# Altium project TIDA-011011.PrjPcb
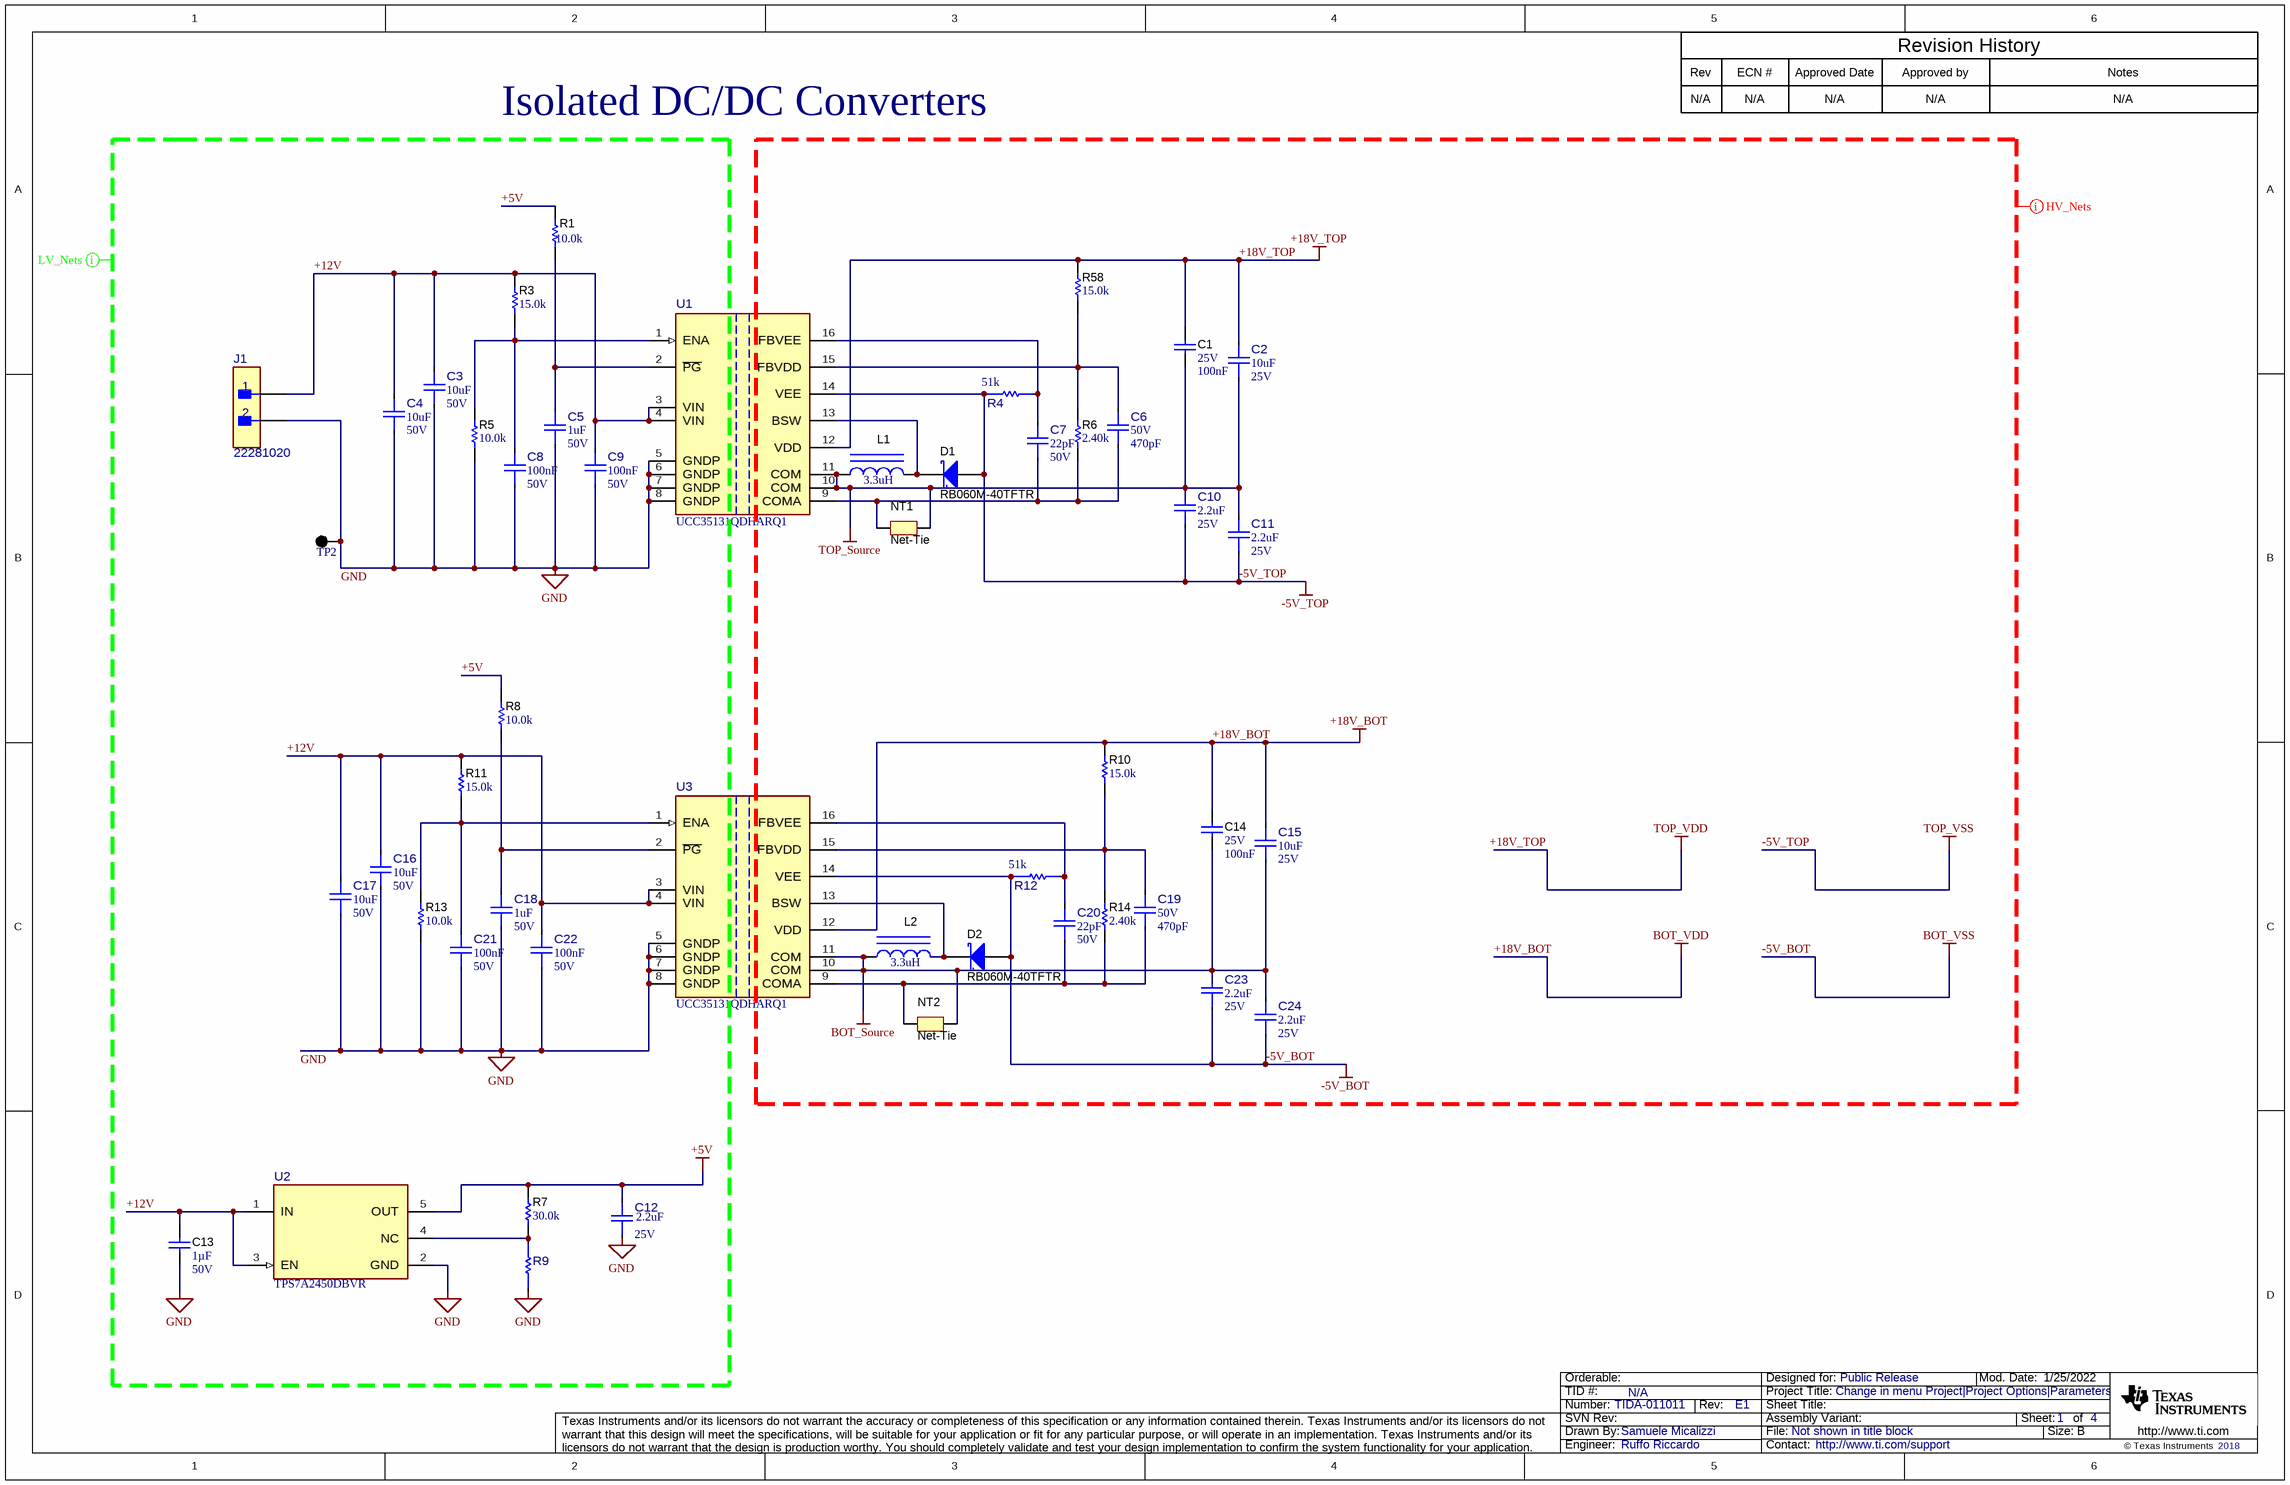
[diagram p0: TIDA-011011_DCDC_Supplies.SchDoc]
DrawnBy: Samuele Micalizzi; TID: N/A; TechSupport: http://www.ti.com/support; SCH_Rev: E1; PRJ_Title: Change in menu Project|Project Options|Parameters; PRJ_Number: TIDA-011011; PRJ_Engineer: Ruffo Riccardo; PRJ_Customer: Public Release; PCB_Rev: E1; PCB_Layout: Samuele Micalizzi; CopyrightYear: 2018
4 sheets, 172 parts. Net scope: global (net labels, ports and power ports of the same name join across sheets).
Board file: TIDA-011011.PcbDoc
Sheets:
  TIDA-011011_DCDC_Supplies.SchDoc
  TIDA-011011_Gate_Drivers.SchDoc
  TIDA-011011_BlankSheet.SchDoc
  TIDA-011011_Hardware.SchDoc

## Sheet TIDA-011011_DCDC_Supplies.SchDoc
size 431 x 279 mm; Date: Not shown in title block; ApprovedBy: Not shown in title block; CheckedBy: Not shown in title block; Author: Not shown in title block; CompanyName: Not shown in title block; Engineer: Not shown in title block; Organization: Not shown in title block; Address1: Not shown in title block; Address2: Not shown in title block; Address3: Not shown in title block; Address4: Not shown in title block; DocumentNumber: 1; Revision: Use project parameter SCH_Rev; SheetNumber: 1; SheetTotal: 4; PageSetup: Record=PageOptions¦CenterHorizontal=True¦CenterVertical=True¦PrintScale=1.00¦XCorrection=1.00¦YCorrection=1.00¦PrintKind=0¦BorderSize=5000000¦LeftOffset=0¦BottomOffset=0¦Orientation=2¦PaperLength=1000¦PaperWidth=1000¦Scale=100¦PaperSource=15¦PrintQuality=600¦MediaType=1¦DitherType=10¦PaperKind=Letter¦PrintScaleMode=1

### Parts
C1  VDC_V: 25V  Cap_F: 100nF  [0603]  (hidden comment: GCM188R71E104KA57D)
C2  ValueDisplayed: 10uF  VDC_V: 25V  [FP-KGM31HR71E106KU_1206-MFG]  (hidden comment: KGM31HR71E106KU)
C3  ValueDisplayed: 10uF  VDC_V: 50V  [FP-GMC31X7R106K50NT_1206-MFG]  (hidden comment: GMC31X7R106K50NT)
C4  ValueDisplayed: 10uF  VDC_V: 50V  [FP-GMC31X7R106K50NT_1206-MFG]  (hidden comment: GMC31X7R106K50NT)
C5  ValueDisplayed: 1uF  VDC_V: 50V  [FP-C1206C105J5RECAUTO_1206-MFG]  (hidden comment: C1206C105J5RECAUTO)
C6  VDC_V: 50V  ValueDisplayed: 470pF  [FP-C0603X471F5GACTU_0603-MFG]  (hidden comment: C0603X471F5GACTU)
C7  ValueDisplayed: 22pF  VDC_V: 50V  [FP-VJ0603D220JLAAJ32_0603-IPC_C]  (hidden comment: VJ0603D220JLAAJ32)
C8  Cap_F: 100nF  VDC_V: 50V  [FP-KGM15BR71H104JT_0603-MFG]  (hidden comment: KGM15BR71H104JT)
C9  Cap_F: 100nF  VDC_V: 50V  [FP-KGM15BR71H104JT_0603-MFG]  (hidden comment: KGM15BR71H104JT)
C10  ValueDisplayed: 2.2uF  VDC_V: 25V  [FP-GRT188C71E225KE13D_0603-MFG]  (hidden comment: GRT188C71E225KE13D)
C11  ValueDisplayed: 2.2uF  VDC_V: 25V  [FP-CGA5L2X7R1E225K160AA_1206-MFG]  (hidden comment: CGA5L2X7R1E225K160AA)
C12  ValueDisplayed: 2.2uF  VDC_V: 25V  [FP-GRT188C71E225KE13D_0603-MFG]  (hidden comment: GRT188C71E225KE13D)
C13  Cap_F: 1µF  VDC_V: 50V  [0603]  (hidden comment: UMK107AB7105KA-T)
C14  VDC_V: 25V  Cap_F: 100nF  [0603]  (hidden comment: GCM188R71E104KA57D)
C15  ValueDisplayed: 10uF  VDC_V: 25V  [FP-KGM31HR71E106KU_1206-MFG]  (hidden comment: KGM31HR71E106KU)
C16  ValueDisplayed: 10uF  VDC_V: 50V  [FP-GMC31X7R106K50NT_1206-MFG]  (hidden comment: GMC31X7R106K50NT)
C17  ValueDisplayed: 10uF  VDC_V: 50V  [FP-GMC31X7R106K50NT_1206-MFG]  (hidden comment: GMC31X7R106K50NT)
C18  ValueDisplayed: 1uF  VDC_V: 50V  [FP-C1206C105J5RECAUTO_1206-MFG]  (hidden comment: C1206C105J5RECAUTO)
C19  VDC_V: 50V  ValueDisplayed: 470pF  [FP-C0603X471F5GACTU_0603-MFG]  (hidden comment: C0603X471F5GACTU)
C20  ValueDisplayed: 22pF  VDC_V: 50V  [FP-VJ0603D220JLAAJ32_0603-IPC_C]  (hidden comment: VJ0603D220JLAAJ32)
C21  Cap_F: 100nF  VDC_V: 50V  [FP-KGM15BR71H104JT_0603-MFG]  (hidden comment: KGM15BR71H104JT)
C22  Cap_F: 100nF  VDC_V: 50V  [FP-KGM15BR71H104JT_0603-MFG]  (hidden comment: KGM15BR71H104JT)
C23  ValueDisplayed: 2.2uF  VDC_V: 25V  [FP-GRT188C71E225KE13D_0603-MFG]  (hidden comment: GRT188C71E225KE13D)
C24  ValueDisplayed: 2.2uF  VDC_V: 25V  [FP-CGA5L2X7R1E225K160AA_1206-MFG]  (hidden comment: CGA5L2X7R1E225K160AA)
D1  RB060M-40TFTR  [SOD-123]
D2  RB060M-40TFTR  [SOD-123]
J1  22281020  [FP-22281020_HDR2-MFG]
L1  ValueDisplayed: 3.3uH  [0603]  (hidden comment: AIML-0603-3R3K-T)
L2  ValueDisplayed: 3.3uH  [0603]  (hidden comment: AIML-0603-3R3K-T)
NT1  Net-Tie  [Net-Tie_0805_HV_NoOverlay]  (net tie, no BOM)
NT2  Net-Tie  [Net-Tie_0805_HV_NoOverlay]  (net tie, no BOM)
R1  ValueDisplayed: 10.0k  [0603]  (hidden comment: RT0603DRE0710KL)
R3  ValueDisplayed: 15.0k  [0603]  (hidden comment: RT0603BRD0715KL)
R4  value 51k  [FP-ERA-3AED513V_0603-MFG]  (hidden comment: ERA-3AED513V)
R5  ValueDisplayed: 10.0k  [0603]  (hidden comment: RT0603DRE0710KL)
R6  ValueDisplayed: 2.40k  [0603]  (hidden comment: RT0603DRE072K4L)
R7  ValueDisplayed: 30.0k  [0603]  (hidden comment: RG1608P-303-B-T5)
R8  ValueDisplayed: 10.0k  [0603]  (hidden comment: RT0603DRE0710KL)
R9  P2TC0603D1002LNTA  [FP-P2TC0603D1002LNTA_0603-MFG]  (value not drawn)
R10  ValueDisplayed: 15.0k  [0603]  (hidden comment: RT0603BRD0715KL)
R11  ValueDisplayed: 15.0k  [0603]  (hidden comment: RT0603BRD0715KL)
R12  value 51k  [FP-ERA-3AED513V_0603-MFG]  (hidden comment: ERA-3AED513V)
R13  ValueDisplayed: 10.0k  [0603]  (hidden comment: RT0603DRE0710KL)
R14  ValueDisplayed: 2.40k  [0603]  (hidden comment: RT0603DRE072K4L)
R58  ValueDisplayed: 15.0k  [0603]  (hidden comment: RT0603BRD0715KL)
TP2  5011  [Keystone5011]  (value not drawn)
U1  UCC35131QDHARQ1  [DHA0016A-MFG]
U2  TPS7A2450DBVR  [DBV0005A-MFG]
U3  UCC35131QDHARQ1  [DHA0016A-MFG]

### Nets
+5V: C12.2 R1.2 R7.2 R8.2 U2.5(OUT)
+12V: C3.2 C4.2 C9.2 C13.1 C16.2 C17.2 C22.2 J1.1 R3.2 R11.2 U1.3(VIN) U1.4(VIN) U2.1(IN) U2.3(EN) U3.3(VIN) U3.4(VIN)
+18V_BOT: C14.1 C15.2 R10.2 U3.12(VDD)  [also labelled BOT_VDD]
+18V_TOP: C1.1 C2.2 R58.2 U1.12(VDD)  [also labelled TOP_VDD]
-5V_BOT: C23.1 C24.1 D2.2(A) R12.1 U3.14(VEE)  [also labelled BOT_VSS]
-5V_TOP: C10.1 C11.1 D1.2(A) R4.1 U1.14(VEE)  [also labelled TOP_VSS]
BOT_Source: C14.2 C15.1 C23.2 C24.2 L2.1 NT2.2 U3.10(COM) U3.11(COM)
GND: C3.1 C4.1 C5.1 C8.1 C9.1 C12.1 C13.2 C16.1 C17.1 C18.1 C21.1 C22.1 J1.2 R5.1 R9.1 R13.1 TP2.1 U1.5(GNDP) U1.6(GNDP) U1.7(GNDP) U1.8(GNDP) U2.2(GND) U3.5(GNDP) U3.6(GNDP) U3.7(GNDP) U3.8(GNDP)
TOP_Source: C1.2 C2.1 C10.2 C11.2 L1.1 NT1.2 U1.10(COM) U1.11(COM)
NetC5_2: C5.2 R1.1 U1.2(~{PG})
NetC6_1: C6.1 C7.1 NT1.1 R6.1 U1.9(COMA)
NetC6_2: C6.2 R6.2 R58.1 U1.15(FBVDD)
NetC7_2: C7.2 R4.2 U1.16(FBVEE)
NetC8_2: C8.2 R3.1 R5.2 U1.1(ENA)
NetC18_2: C18.2 R8.1 U3.2(~{PG})
NetC19_1: C19.1 C20.1 NT2.1 R14.1 U3.9(COMA)
NetC19_2: C19.2 R10.1 R14.2 U3.15(FBVDD)
NetC20_2: C20.2 R12.2 U3.16(FBVEE)
NetC21_2: C21.2 R11.1 R13.2 U3.1(ENA)
NetD1_1: D1.1(K) L1.2 U1.13(BSW)
NetD2_1: D2.1(K) L2.2 U3.13(BSW)
NetR7_1: R7.1 R9.2 U2.4(NC)

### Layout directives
mark named LV_Nets: +5V, +12V, GND
mark named HV_Nets: +18V_BOT, +18V_TOP, -5V_BOT, -5V_TOP, BOT_Source, BOT_VDD, BOT_VSS, TOP_Source, TOP_VDD, TOP_VSS

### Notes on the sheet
- Rev
- N/A
- ECN #
- Approved Date
- Approved by
- Revision History
- Notes
- Isolated DC/DC Converters

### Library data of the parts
C1 C14 = CMP-0084679-1: CAP, CERM, 0.1 µF, 25 V,+/- 10%, X7R, AEC-Q200 Grade 1, 0603; Manufacturer: MuRata; TaMin_C: -55°C; SizeY_mm: 0.8; Polarized: N; SizeArea_mm2: 1.28; SizeZ_mm: 1; SizeX_mm: 1.6; AEC Qualified: Y; AEC Category: Q200; Value: 0.1uF; ValueDisplayed: 0.1µF; TaMax_C: 125°C; U/M: EA; SizeAreaWB_mm2: 4.68
C2 C15 = CMP-0044202-1: 10 µF ±10% 25V Ceramic Capacitor X7R 1206 (3216 Metric); Manufacturer: KYOCERA AVX; AEC Qualified: No; Cap_F: 10µF; SizeZ_mm: 1.9mm; TempCo: 15%; Value: 10µF
C3 C4 C16 C17 = CMP-0093201-1: 10 µF ±10% 50V Ceramic Capacitor X7R 1206 (3216 Metric); Manufacturer: Cal-Chip Electronics; AEC Qualified: No; SizeZ_mm: 1.8mm; TempCo: 15%; Value: 10µF
C5 C18 = CMP-0094524-1: 1 µF ±5% 50V Ceramic Capacitor X7R 1206 (3216 Metric); Manufacturer: KEMET; TempCo: 15%; Cap_F: 1µF; AEC Grade: Grade 1; AEC Qualified: Yes; SizeZ_mm: 1.1mm; Value: 1µF
C6 C19 = CMP-0097612-1: Cap Ceramic 470pF 50V C0G 1% SMD 0603 125°C Paper T/R; Manufacturer: KEMET; SizeZ_mm: 0.95mm; TempCo: 30ppm/°C; AEC Qualified: No
C7 C20 = CMP-0039814-1: 22 pF ±5% 50V Ceramic Capacitor C0G, NP0 0603 (1608 Metric); Manufacturer: Vishay; AEC Grade: Grade 0; AEC Qualified: Yes; SizeZ_mm: 0.97mm; TempCo: 30ppm/°C; Value: 22pF
C8 C9 C21 C22 = CMP-0120061-1: 0.1 µF ±5% 50V Ceramic Capacitor X7R 0603 (1608 Metric); Manufacturer: KYOCERA AVX; AEC Qualified: No; SizeZ_mm: 0.94mm; TempCo: 15%; ValueDisplayed: 0.1uF; Value: 100nF
C10 C12 C23 = CMP-0125378-1: Multi-Layer Ceramic Capacitor 2.2uF 25V X7S ±10% 0603 Paper T/R; Manufacturer: Murata; AEC Grade: Grade 1; AEC Qualified: Yes; Cap_F: 2.2µF; SizeZ_mm: 1mm; TempCo: 22%; Value: 2.2µF
C11 C24 = CMP-0090741-1: Cap Ceramic 2.2uF 25V X7R 10% Pad SMD 1206 +125°C Automotive T/R; Manufacturer: TDK; Cap_F: 2.2µF; Value: 2.2µF; Tolerance_%: 0.1%; TempCo: 15%; AEC Grade: Grade 1; AEC Qualified: Yes; SizeZ_mm: 1.9mm
C13 = CMP-0007508-5: CAP, CERM, 1 uF, 50 V, +/- 10%, X7R, 0603; Manufacturer: Taiyo Yuden; TaMin_C: -55°C; Polarized: N; SizeAreaWB_mm2: 4.68; Value1: Unknown; U/M: EA; Value: 1uF; TaMax_C: 125°C; SizeZ_mm: 1; SizeX_mm: 1.6; SizeY_mm: 0.8; SizeArea_mm2: 1.28; AEC Category: Q200
D1 D2 = CMP-0028628-2: Diode, Schottky, 40 V, 2 A, SOD-123; Manufacturer: Rohm; Green_REACh: Incomplete; SizeX_mm: 3.85; SizeZ_mm: 1.35; TJmax_C: 150°C; Value1: 2A; SizeAreaWB_mm2: 13.095; SizeArea_mm2: 6.545; AEC Category: Q101; Value2: 0.56V; SizeY_mm: 1.7; Value: 40V; Vf_V: 560mV; Green_Lifecycle: Not Set
J1 = CMP-0092582-1: KK 254 Breakaway Header, Right-Angle with Friction Lock, 2 Circuits, Tin (Sn) Plating; Manufacturer: Molex; Current_A: 4A; Row_Count: 1; AEC Qualified: No; Voltage_V: 500V; Conn Gender: Male; Conn Orientation: Right Angle; SizeZ_mm: 7.46mm; DUT-Pitch_mm: 2.54mm
L1 L2 = CMP-0059575-1: Inductor, Multilayer, Ferrite, 3.3 uH, 0.015 A, 1.55 ohm, SMD; Manufacturer: Abracon Corporation; Green_Lifecycle: Active; SizeAreaWB_mm2: 4.68; DCR_ohm: 1.55; Green_REACh: Passed; Value: 3.3uH; Imax_A: 15mA; SizeZ_mm: 1; SizeX_mm: 1.6; SizeY_mm: 0.8; Value2: 0.015A; SizeArea_mm2: 1.28; Ind_H: 3.3µH; AEC Qualified: N; AEC Category: Q200
NT1 NT2 = CMP-0078142-6: Single point connection between nets.
R1 R5 R8 R13 = CMP-0024586-3: RES, 10.0 k, 0.5%, 0.1 W, 0603; Manufacturer: Yageo America; Power_W: 100mW; TempCo: 50 ppm/C; Value_Code: 10k0; U/M: EA; Value: 10.0k; EIA_Code: E192; Res_ohm: 10k; SizeX_mm: 1.6; SizeY_mm: 0.8; SizeZ_mm: 1; Value2: 0.1W; SizeArea_mm2: 1.28; VDC_V: 75V; AEC Category: Q200
R3 R10 R11 R58 = CMP-0023780-3: RES, 15.0 k, 0.1%, 0.1 W, 0603; Manufacturer: Yageo America; Power_W: 100mW; TempCo: 25 ppm/C; Value_Code: 15k0; U/M: EA; Value: 15.0k; EIA_Code: E192; Res_ohm: 15k; SizeX_mm: 1.6; SizeY_mm: 0.8; SizeZ_mm: 1; Value2: 0.1W; SizeArea_mm2: 1.28; VDC_V: 75V; AEC Category: Q200
R4 R12 = CMP-0031881-1: 51 kOhms ±0.5% 0.1W, 1/10W Chip Resistor 0603 (1608 Metric) Automotive AEC-Q200 Thin Film; Manufacturer: Panasonic; AEC Grade: Grade 0; AEC Qualified: Yes; Power_W: 100mW; SizeZ_mm: 0.55mm; TempCo: 25ppm/°C; VDC_V: 75V
R6 R14 = CMP-0025064-3: RES, 2.40 k, 0.5%, 0.1 W, 0603; Manufacturer: Yageo America; Power_W: 100mW; TempCo: 50 ppm/C; Value_Code: 2k40; U/M: EA; Value: 2.40k; EIA_Code: E192; Res_ohm: 2.4k; SizeX_mm: 1.6; SizeY_mm: 0.8; SizeZ_mm: 1; Value2: 0.1W; SizeArea_mm2: 1.28; VDC_V: 75V; AEC Category: Q200
R7 = CMP-0023508-3: RES, 30.0 k, 0.1%, 0.1 W, 0603; Manufacturer: Susumu Co Ltd; Power_W: 100mW; TempCo: 25 ppm/C; Value_Code: 30k0; U/M: EA; Value: 30.0k; Res_ohm: 30k; SizeX_mm: 1.6; SizeY_mm: 0.8; SizeZ_mm: 1; Value2: 0.1W; SizeArea_mm2: 1.28; VDC_V: 75V; AEC Category: Q200
R9 = CMP-0126340-1: 10 kOhms ±0.01% 0.125W, 1/8W Chip Resistor 0603 (1608 Metric) Anti-Sulfur, Moisture Resistant Thin Film; Manufacturer: Vishay; AEC Qualified: No; Power_W: 125mW; Res_ohm: 10k; SizeZ_mm: 0.627mm; TempCo: 2ppm/°C; VDC_V: 75V; Value: 10k
TP2 = CMP-0055148-2: Test Point, Multipurpose, Black, TH; Manufacturer: Keystone Electronics; CNHeader: FALSE; ContactFinish: Silver; Green_REACh: Passed; Green_Lifecycle: Active; CT: TRUE
U1 U3 = CMP-0126653-2: Automotive 2.0W, 12V VIN, High-Density, > 5kVRMS, Isolated DC/DC Module; Manufacturer: Texas Instruments; SizeZ_mm: 2.6mm; AEC Qualified: Yes; AEC Grade: Grade 1; Max Supply Voltage: 20V; Min Supply Voltage: 5.5V; Number Of Outputs: 2; Output Type: AdjustableProgrammable; Output Voltage: -2-8/12-18V; Standoff Height: 0.1mm; TaMax_C: +125°C; TaMin_C: -40°C; TJmax_C: +150°C; AEC Category: Q200; CompType: IC
U2 = CMP-0096923-1: Linear Voltage Regulator IC  1 Output  200mA SOT-23-5; Manufacturer: Texas Instruments; AEC Qualified: No; Standoff Height: 0mm; Accuracy Percentage: 2%; SizeZ_mm: 1.45mm; Number Of Outputs: 1; TJmax_C: +125°C; Max Supply Voltage: 18V; Output Type: Fixed; Nominal Supply Current: 2-15uA; Dropout Voltage: 160mV; Output Voltage: 5V; Min Supply Voltage: 2.4V

## Sheet TIDA-011011_Gate_Drivers.SchDoc
size 558 x 431 mm; Date: Not shown in title block; ApprovedBy: Not shown in title block; CheckedBy: Not shown in title block; Author: Not shown in title block; CompanyName: Not shown in title block; Engineer: Not shown in title block; Organization: Not shown in title block; Address1: Not shown in title block; Address2: Not shown in title block; Address3: Not shown in title block; Address4: Not shown in title block; DocumentNumber: 1; Revision: Use project parameter SCH_Rev; SheetNumber: 2; SheetTotal: 4; PageSetup: Record=PageOptions¦CenterHorizontal=True¦CenterVertical=True¦PrintScale=1.00¦XCorrection=1.00¦YCorrection=1.00¦PrintKind=0¦BorderSize=5000000¦LeftOffset=0¦BottomOffset=0¦Orientation=2¦PaperLength=1000¦PaperWidth=1000¦Scale=100¦PaperSource=15¦PrintQuality=600¦MediaType=1¦DitherType=10¦PaperKind=Letter¦PrintScaleMode=1
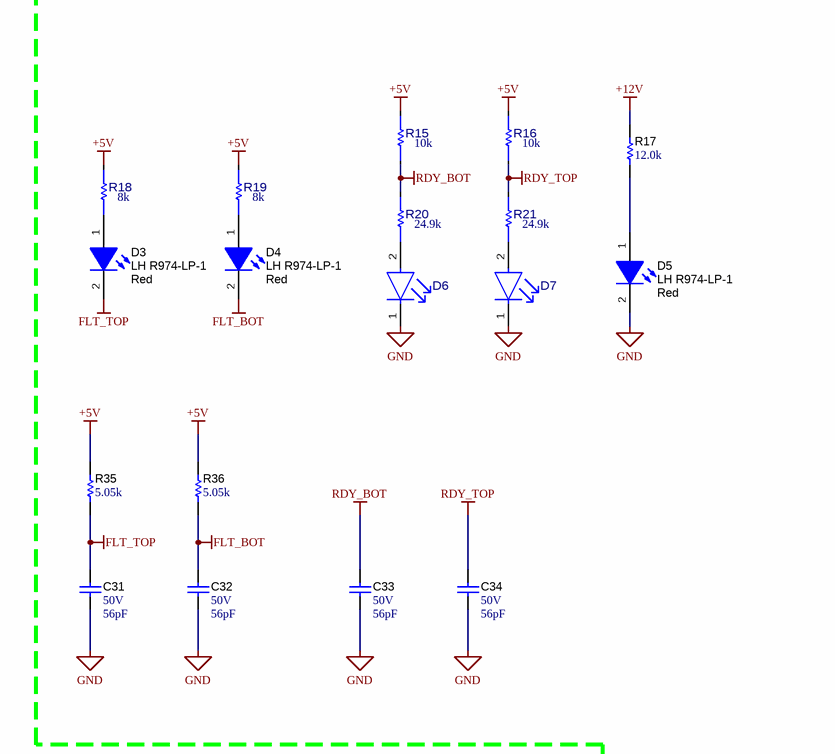
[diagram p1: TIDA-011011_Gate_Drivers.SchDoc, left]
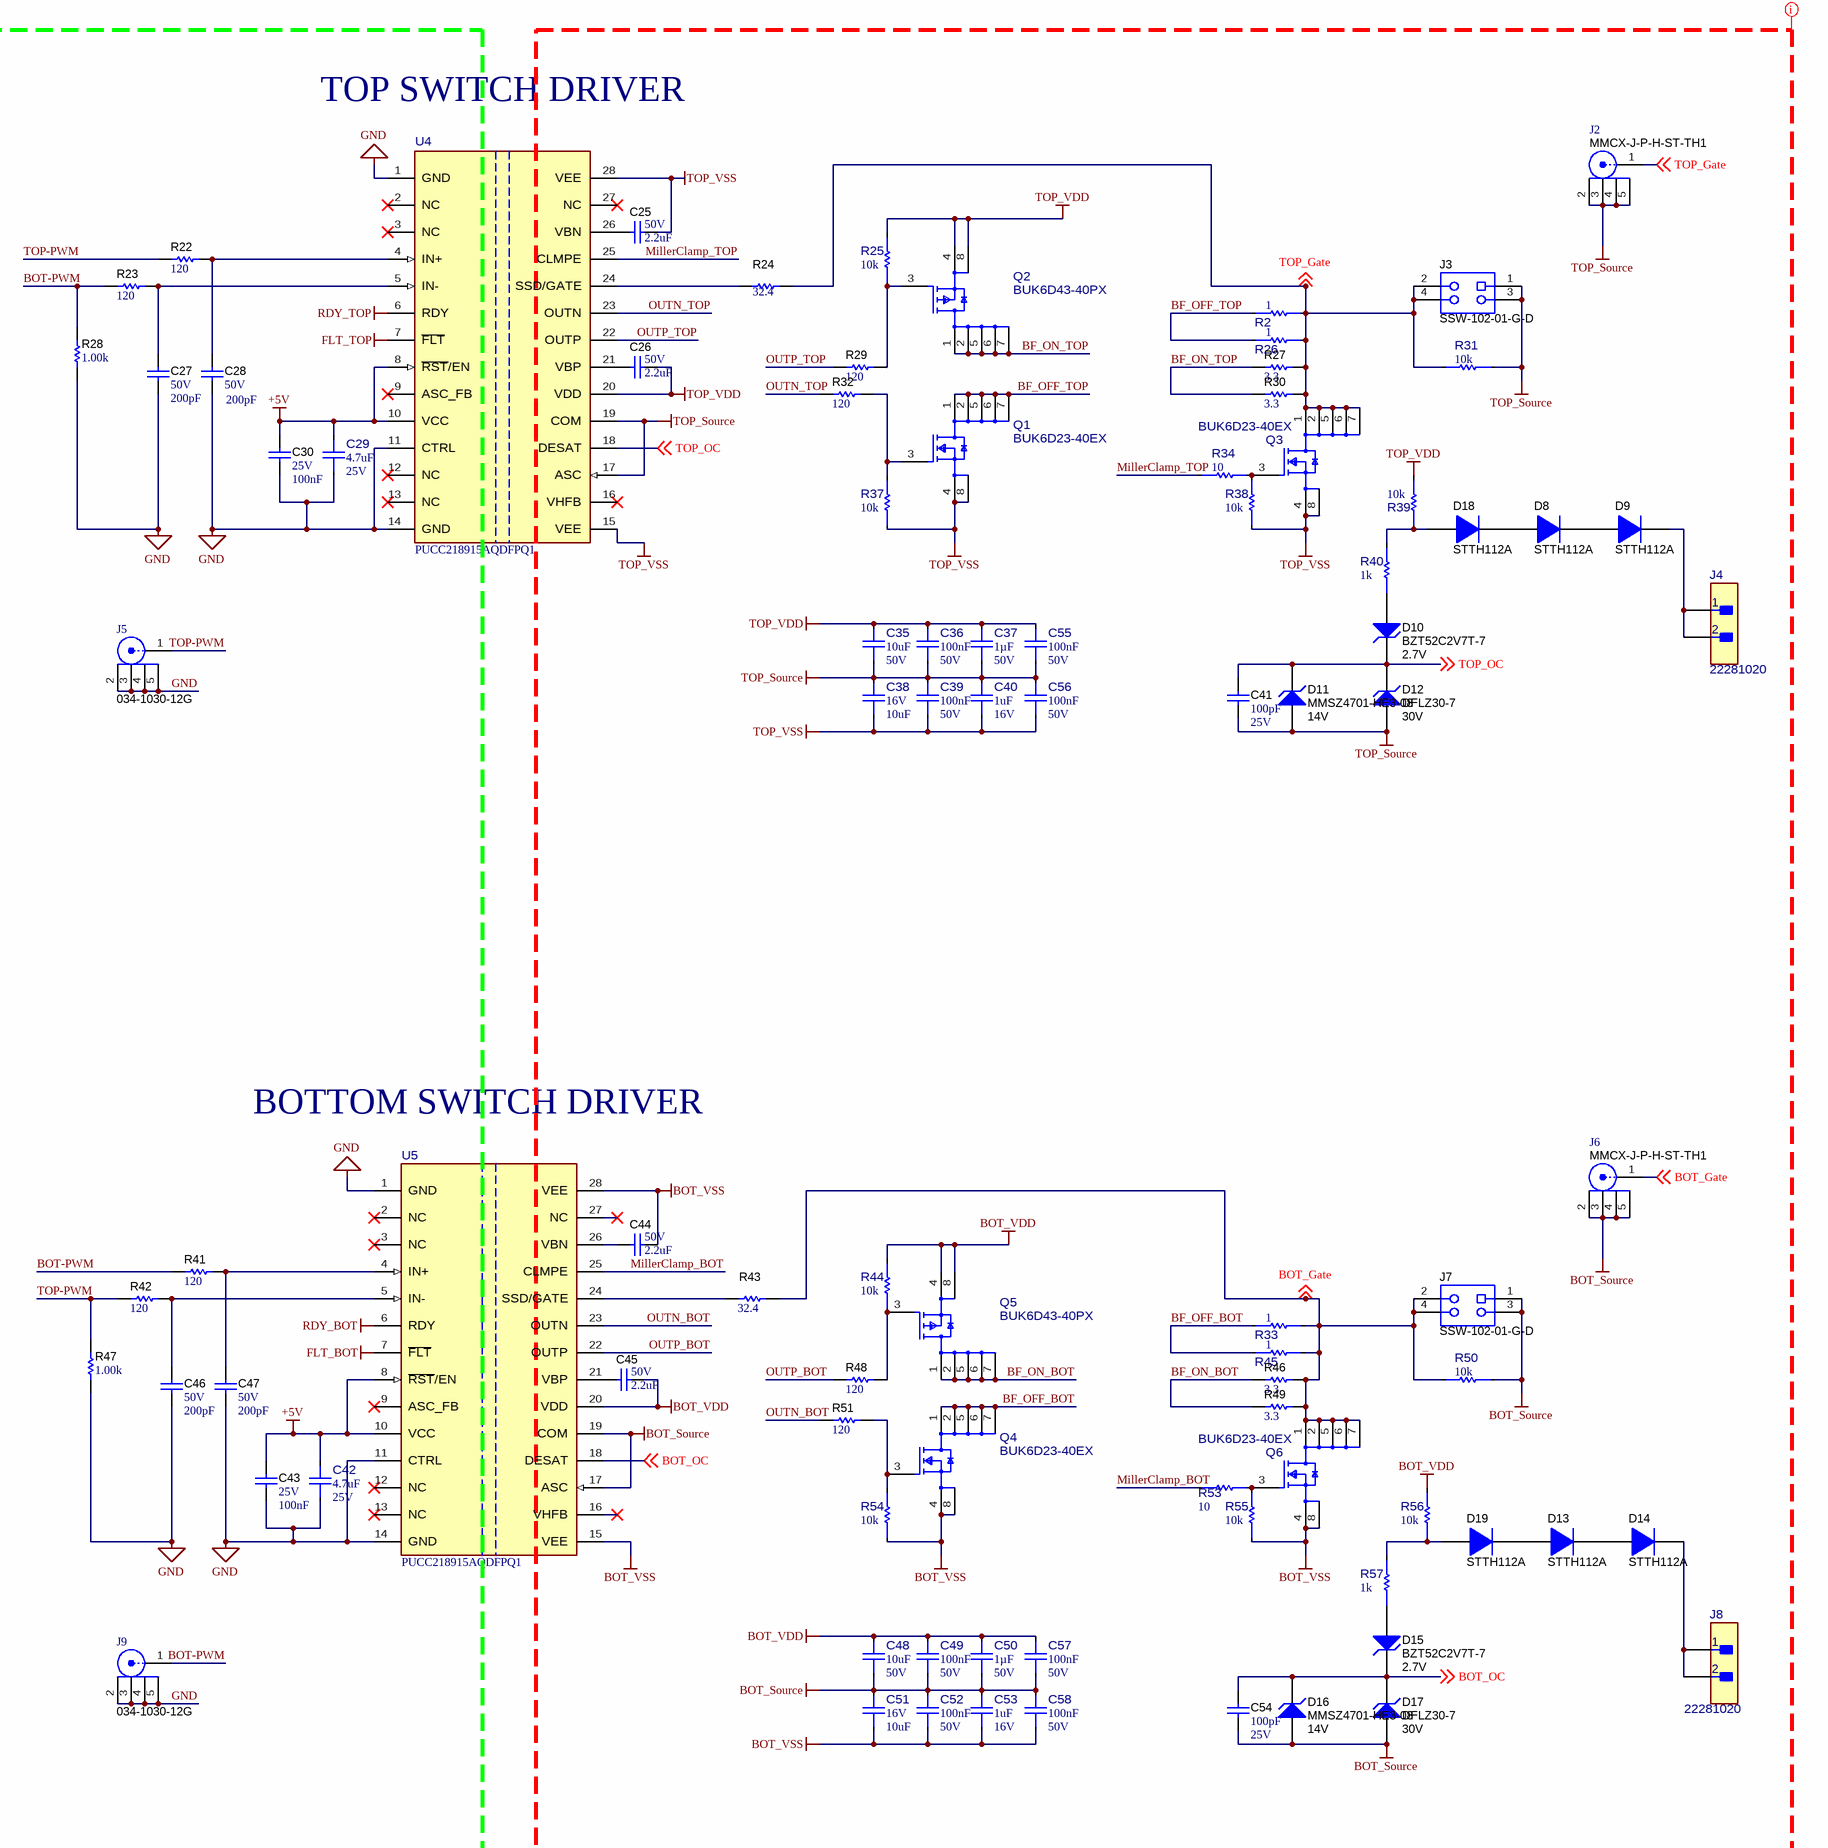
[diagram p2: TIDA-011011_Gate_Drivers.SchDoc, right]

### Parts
C25  VDC_V: 50V  ValueDisplayed: 2.2uF  [0603]  (hidden comment: GRT188R61H225KE13D)
C26  VDC_V: 50V  ValueDisplayed: 2.2uF  [0603]  (hidden comment: GRT188R61H225KE13D)
C27  VDC_V: 50V  ValueDisplayed: 200pF  [0603]  (hidden comment: GRM1885C1H201JA01D)
C28  VDC_V: 50V  ValueDisplayed: 200pF  [0603]  (hidden comment: GRM1885C1H201JA01D)
C29  ValueDisplayed: 4.7uF  VDC_V: 25V  [FP-GRM188R61E475KE15D_0603-MFG]  (hidden comment: GRM188R61E475KE15D)
C30  VDC_V: 25V  Cap_F: 100nF  [0603]  (hidden comment: GCM188R71E104KA57D)
C31  VDC_V: 50V  ValueDisplayed: 56pF  [0603]  (hidden comment: 06035A560FAT2A)
C32  VDC_V: 50V  ValueDisplayed: 56pF  [0603]  (hidden comment: 06035A560FAT2A)
C33  VDC_V: 50V  ValueDisplayed: 56pF  [0603]  (hidden comment: 06035A560FAT2A)
C34  VDC_V: 50V  ValueDisplayed: 56pF  [0603]  (hidden comment: 06035A560FAT2A)
C35  ValueDisplayed: 10uF  VDC_V: 50V  [FP-GMC31X7R106K50NT_1206-MFG]  (hidden comment: GMC31X7R106K50NT)
C36  Cap_F: 100nF  VDC_V: 50V  [FP-C0805C104K5RAC7800_0805-MFG]  (hidden comment: C0805C104K5RAC7800)
C37  Cap_F: 1µF  VDC_V: 50V  [FP-CL10B105KB9VPJC_0603-MFG]  (hidden comment: CL10B105KB9VPJC)
C38  VDC_V: 16V  ValueDisplayed: 10uF  [FP-C1206C106J4RACAUTO_1206-MFG]  (hidden comment: C1206C106J4RACAUTO)
C39  Cap_F: 100nF  VDC_V: 50V  [FP-C0805C104K5RAC7800_0805-MFG]  (hidden comment: C0805C104K5RAC7800)
C40  ValueDisplayed: 1uF  VDC_V: 16V  [FP-GRM188C71C105KA12D_0603-MFG]  (hidden comment: GRM188C71C105KA12D)
C41  Cap_F: 100pF  VDC_V: 25V  [0603]  (hidden comment: 06033C101KAT2A)
C42  ValueDisplayed: 4.7uF  VDC_V: 25V  [FP-GRM188R61E475KE15D_0603-MFG]  (hidden comment: GRM188R61E475KE15D)
C43  VDC_V: 25V  Cap_F: 100nF  [0603]  (hidden comment: GCM188R71E104KA57D)
C44  VDC_V: 50V  ValueDisplayed: 2.2uF  [0603]  (hidden comment: GRT188R61H225KE13D)
C45  VDC_V: 50V  ValueDisplayed: 2.2uF  [0603]  (hidden comment: GRT188R61H225KE13D)
C46  VDC_V: 50V  ValueDisplayed: 200pF  [0603]  (hidden comment: GRM1885C1H201JA01D)
C47  VDC_V: 50V  ValueDisplayed: 200pF  [0603]  (hidden comment: GRM1885C1H201JA01D)
C48  ValueDisplayed: 10uF  VDC_V: 50V  [FP-GMC31X7R106K50NT_1206-MFG]  (hidden comment: GMC31X7R106K50NT)
C49  Cap_F: 100nF  VDC_V: 50V  [FP-C0805C104K5RAC7800_0805-MFG]  (hidden comment: C0805C104K5RAC7800)
C50  Cap_F: 1µF  VDC_V: 50V  [FP-CL10B105KB9VPJC_0603-MFG]  (hidden comment: CL10B105KB9VPJC)
C51  VDC_V: 16V  ValueDisplayed: 10uF  [FP-C1206C106J4RACAUTO_1206-MFG]  (hidden comment: C1206C106J4RACAUTO)
C52  Cap_F: 100nF  VDC_V: 50V  [FP-C0805C104K5RAC7800_0805-MFG]  (hidden comment: C0805C104K5RAC7800)
C53  ValueDisplayed: 1uF  VDC_V: 16V  [FP-GRM188C71C105KA12D_0603-MFG]  (hidden comment: GRM188C71C105KA12D)
C54  Cap_F: 100pF  VDC_V: 25V  [0603]  (hidden comment: 06033C101KAT2A)
C55  Cap_F: 100nF  VDC_V: 50V  [FP-C0603C104K5RAC3121_0603-MFG]  (hidden comment: C0603C104K5RAC3121)
C56  Cap_F: 100nF  VDC_V: 50V  [FP-C0603C104K5RAC3121_0603-MFG]  (hidden comment: C0603C104K5RAC3121)
C57  Cap_F: 100nF  VDC_V: 50V  [FP-C0603C104K5RAC3121_0603-MFG]  (hidden comment: C0603C104K5RAC3121)
C58  Cap_F: 100nF  VDC_V: 50V  [FP-C0603C104K5RAC3121_0603-MFG]  (hidden comment: C0603C104K5RAC3121)
D3  LH R974-LP-1  value Red  [LH_R974_Red]
D4  LH R974-LP-1  value Red  [LH_R974_Red]
D5  LH R974-LP-1  value Red  [LH_R974_Red]
D6  KG DELLS1.22-JGKH-24  [FP-KG DELLS1.22-JGKH-24_0603-MFG]  (value not drawn)
D7  KG DELLS1.22-JGKH-24  [FP-KG DELLS1.22-JGKH-24_0603-MFG]  (value not drawn)
D8  STTH112A  [SMA]
D9  STTH112A  [SMA]
D10  BZT52C2V7T-7  value 2.7V  [SOD-523]
D11  MMSZ4701-HE3-08  value 14V  [SOD-123]
D12  DFLZ30-7  value 30V  [PowerDI123]
D13  STTH112A  [SMA]
D14  STTH112A  [SMA]
D15  BZT52C2V7T-7  value 2.7V  [SOD-523]
D16  MMSZ4701-HE3-08  value 14V  [SOD-123]
D17  DFLZ30-7  value 30V  [PowerDI123]
D18  STTH112A  [SMA]
D19  STTH112A  [SMA]
J2  MMCX-J-P-H-ST-TH1  [Samtec_MMCX-J-P-H-ST-TH1]
J3  SSW-102-01-G-D  [Samtec_SSW-102-01-x-D]
J4  22281020  [FP-22281020_HDR2-MFG]
J5  034-1030-12G  [Amphenol_034-1030-12G]
J6  MMCX-J-P-H-ST-TH1  [Samtec_MMCX-J-P-H-ST-TH1]
J7  SSW-102-01-G-D  [Samtec_SSW-102-01-x-D]
J8  22281020  [FP-22281020_HDR2-MFG]
J9  034-1030-12G  [Amphenol_034-1030-12G]
Q1  BUK6D23-40EX  [FP-BUK6D23-40EX_SOT1220-MFG]
Q2  BUK6D43-40PX  [FP-BUK6D43-40PX_SOT1220-MFG]
Q3  BUK6D23-40EX  [FP-BUK6D23-40EX_SOT1220-MFG]
Q4  BUK6D23-40EX  [FP-BUK6D23-40EX_SOT1220-MFG]
Q5  BUK6D43-40PX  [FP-BUK6D43-40PX_SOT1220-MFG]
Q6  BUK6D23-40EX  [FP-BUK6D23-40EX_SOT1220-MFG]
R2  value 1  [FP-TNPW12061R00DEEA_1206-MFG]  (hidden comment: TNPW12061R00DEEA)
R15  value 10k  [FP-560112116005_0603-MFG]  (hidden comment: 560112116005)
R16  value 10k  [FP-560112116005_0603-MFG]  (hidden comment: 560112116005)
R17  ValueDisplayed: 12.0k  [0603]  (hidden comment: ERJ-3EKF1202V)
R18  value 8k  [FP-RT0603BRE078KL_0603-MFG]  (hidden comment: RT0603BRE078KL)
R19  value 8k  [FP-RT0603BRE078KL_0603-MFG]  (hidden comment: RT0603BRE078KL)
R20  value 24.9k  [FP-560112116140_0603-MFG]  (hidden comment: 560112116140)
R21  value 24.9k  [FP-560112116140_0603-MFG]  (hidden comment: 560112116140)
R22  ValueDisplayed: 120  [0603]  (hidden comment: RT0603BRD07120RL)
R23  ValueDisplayed: 120  [0603]  (hidden comment: RT0603BRD07120RL)
R24  ValueDisplayed: 32.4  [1206]  (hidden comment: CRCW120632R4FKEA)
R25  value 10k  [FP-560112116005_0603-MFG]  (hidden comment: 560112116005)
R26  value 1  [FP-TNPW12061R00DEEA_1206-MFG]  (hidden comment: TNPW12061R00DEEA)
R27  ValueDisplayed: 3.3  [1206]  (hidden comment: CRCW12063R30JNEA)
R28  ValueDisplayed: 1.00k  [0603]  (hidden comment: RT0603DRE071KL)
R29  ValueDisplayed: 120  [0603]  (hidden comment: RT0603BRD07120RL)
R30  ValueDisplayed: 3.3  [1206]  (hidden comment: CRCW12063R30JNEA)
R31  value 10k  [FP-560112116005_0603-MFG]  (hidden comment: 560112116005)
R32  ValueDisplayed: 120  [0603]  (hidden comment: RT0603BRD07120RL)
R33  value 1  [FP-TNPW12061R00DEEA_1206-MFG]  (hidden comment: TNPW12061R00DEEA)
R34  value 10  [FP-ESR03EZPF10R0_0603-MFG]  (hidden comment: ESR03EZPF10R0)
R35  ValueDisplayed: 5.05k  [0603]  (hidden comment: RT0603DRE075K05L)
R36  ValueDisplayed: 5.05k  [0603]  (hidden comment: RT0603DRE075K05L)
R37  value 10k  [FP-560112116005_0603-MFG]  (hidden comment: 560112116005)
R38  value 10k  [FP-560112116005_0603-MFG]  (hidden comment: 560112116005)
R39  value 10k  [FP-560112116005_0603-MFG]  (hidden comment: 560112116005)
R40  value 1k  [FP-P2TC0603D1001LNTA_0603-MFG]  (hidden comment: P2TC0603D1001LNTA)
R41  ValueDisplayed: 120  [0603]  (hidden comment: RT0603BRD07120RL)
R42  ValueDisplayed: 120  [0603]  (hidden comment: RT0603BRD07120RL)
R43  ValueDisplayed: 32.4  [1206]  (hidden comment: CRCW120632R4FKEA)
R44  value 10k  [FP-560112116005_0603-MFG]  (hidden comment: 560112116005)
R45  value 1  [FP-TNPW12061R00DEEA_1206-MFG]  (hidden comment: TNPW12061R00DEEA)
R46  ValueDisplayed: 3.3  [1206]  (hidden comment: CRCW12063R30JNEA)
R47  ValueDisplayed: 1.00k  [0603]  (hidden comment: RT0603DRE071KL)
R48  ValueDisplayed: 120  [0603]  (hidden comment: RT0603BRD07120RL)
R49  ValueDisplayed: 3.3  [1206]  (hidden comment: CRCW12063R30JNEA)
R50  value 10k  [FP-560112116005_0603-MFG]  (hidden comment: 560112116005)
R51  ValueDisplayed: 120  [0603]  (hidden comment: RT0603BRD07120RL)
R53  value 10  [FP-ESR03EZPF10R0_0603-MFG]  (hidden comment: ESR03EZPF10R0)
R54  value 10k  [FP-560112116005_0603-MFG]  (hidden comment: 560112116005)
R55  value 10k  [FP-560112116005_0603-MFG]  (hidden comment: 560112116005)
R56  value 10k  [FP-560112116005_0603-MFG]  (hidden comment: 560112116005)
R57  value 1k  [FP-P2TC0603D1001LNTA_0603-MFG]  (hidden comment: P2TC0603D1001LNTA)
U4  PUCC218915AQDFPQ1  [DFP0028A-MFG]
U5  PUCC218915AQDFPQ1  [DFP0028A-MFG]

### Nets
+5V: C29.2 C30.2 C42.2 C43.2 R15.2 R16.2 R18.2 R19.2 R35.2 R36.2 U4.8(~{RST}/EN) U4.10(VCC) U5.8(~{RST}/EN) U5.10(VCC)
+12V: R17.2
BOT_Source: C48.1 C49.1 C50.1 C51.2 C52.2 C53.2 C54.2 C57.1 C58.2 D16.2(A) D17.2(A) J6.2 J6.3 J6.4 J6.5 J7.1 J7.3 R50.1 U5.17(ASC) U5.19(COM)
BOT_VDD: C45.1 C48.2 C49.2 C50.2 C57.2 Q5.4(S) Q5.8(S) R44.2 R56.2 U5.20(VDD)  [project net +18V_BOT]
BOT_VSS: C44.1 C51.1 C52.1 C53.1 C58.1 Q4.4(S) Q4.8(S) Q6.4(S) Q6.8(S) R54.1 R55.1 U5.15(VEE) U5.28(VEE)  [project net -5V_BOT]
FLT_BOT: C32.1 D4.2(K) R36.1 U5.7(~{FLT})
FLT_TOP: C31.1 D3.2(K) R35.1 U4.7(~{FLT})
GND: C27.2 C28.2 C29.1 C30.1 C31.2 C32.2 C33.2 C34.2 C42.1 C43.1 C46.2 C47.2 D5.2(K) D6.1(CATHODE) D7.1(CATHODE) J5.2 J5.3 J5.4 J5.5 J9.2 J9.3 J9.4 J9.5 R28.1 R47.1 U4.1(GND) U4.11(CTRL) U4.14(GND) U5.1(GND) U5.11(CTRL) U5.14(GND)
RDY_BOT: C33.1 R15.1 R20.2 U5.6(RDY)
RDY_TOP: C34.1 R16.1 R21.2 U4.6(RDY)
TOP_Source: C35.1 C36.1 C37.1 C38.2 C39.2 C40.2 C41.2 C55.1 C56.2 D11.2(A) D12.2(A) J2.2 J2.3 J2.4 J2.5 J3.1 J3.3 R31.1 U4.17(ASC) U4.19(COM)
TOP_VDD: C26.1 C35.2 C36.2 C37.2 C55.2 Q2.4(S) Q2.8(S) R25.2 R39.2 U4.20(VDD)  [project net +18V_TOP]
TOP_VSS: C25.1 C38.1 C39.1 C40.1 C56.1 Q1.4(S) Q1.8(S) Q3.4(S) Q3.8(S) R37.1 R38.1 U4.15(VEE) U4.28(VEE)  [project net -5V_TOP]
BF_OFF_BOT: Q4.1(D) Q4.2(D) Q4.5(D) Q4.6(D) Q4.7(D) R33.1 R45.1
BF_OFF_TOP: Q1.1(D) Q1.2(D) Q1.5(D) Q1.6(D) Q1.7(D) R2.1 R26.1
BF_ON_BOT: Q5.1(D) Q5.2(D) Q5.5(D) Q5.6(D) Q5.7(D) R46.1 R49.1
BF_ON_TOP: Q2.1(D) Q2.2(D) Q2.5(D) Q2.6(D) Q2.7(D) R27.1 R30.1
BOT-PWM: J9.1 R23.1 R28.2 R41.1
BOT_Gate: J6.1 J7.2 J7.4 Q6.1(D) Q6.2(D) Q6.5(D) Q6.6(D) Q6.7(D) R33.2 R43.2 R45.2 R46.2 R49.2 R50.2 ; off-sheet BOT_Gate
BOT_OC: C54.1 D15.1(K) D16.1(K) D17.1(K) U5.18(DESAT) ; off-sheet BOT_OC
MillerClamp_BOT: R53.1 U5.25(CLMPE)
MillerClamp_TOP: R34.1 U4.25(CLMPE)
OUTN_BOT: R51.1 U5.23(OUTN)
OUTN_TOP: R32.1 U4.23(OUTN)
OUTP_BOT: R48.1 U5.22(OUTP)
OUTP_TOP: R29.1 U4.22(OUTP)
TOP-PWM: J5.1 R22.1 R42.1 R47.2
TOP_Gate: J2.1 J3.2 J3.4 Q3.1(D) Q3.2(D) Q3.5(D) Q3.6(D) Q3.7(D) R2.2 R24.2 R26.2 R27.2 R30.2 R31.2 ; off-sheet TOP_Gate
TOP_OC: C41.1 D10.1(K) D11.1(K) D12.1(K) U4.18(DESAT) ; off-sheet TOP_OC
NetC25_2: C25.2 U4.26(VBN)
NetC26_2: C26.2 U4.21(VBP)
NetC27_1: C27.1 R23.2 U4.5(IN-)
NetC28_1: C28.1 R22.2 U4.4(IN+)
NetC44_2: C44.2 U5.26(VBN)
NetC45_2: C45.2 U5.21(VBP)
NetC46_1: C46.1 R42.2 U5.5(IN-)
NetC47_1: C47.1 R41.2 U5.4(IN+)
NetD3_1: D3.1(A) R18.1
NetD4_1: D4.1(A) R19.1
NetD5_1: D5.1(A) R17.1
NetD6_2: D6.2(ANODE) R20.1
NetD7_2: D7.2(ANODE) R21.1
NetD8_1: D8.1(K) D9.2(A)
NetD8_2: D8.2(A) D18.1(K)
NetD9_1: D9.1(K) J4.1 J4.2
NetD10_2: D10.2(A) R40.1
NetD13_1: D13.1(K) D14.2(A)
NetD13_2: D13.2(A) D19.1(K)
NetD14_1: D14.1(K) J8.1 J8.2
NetD15_2: D15.2(A) R57.1
NetD18_2: D18.2(A) R39.1 R40.2
NetD19_2: D19.2(A) R56.1 R57.2
NetQ1_3: Q1.3(G) R32.2 R37.2
NetQ2_3: Q2.3(G) R25.1 R29.2
NetQ3_3: Q3.3(G) R34.2 R38.2
NetQ4_3: Q4.3(G) R51.2 R54.2
NetQ5_3: Q5.3(G) R44.1 R48.2
NetQ6_3: Q6.3(G) R53.2 R55.2
NetR24_1: R24.1 U4.24(SSD/GATE)
NetR43_1: R43.1 U5.24(SSD/GATE)

Not connected (* = marked no-connect by the designer): U4 2(NC)* 3(NC)* 9(ASC_FB)* 12(NC)* 13(NC)* 16(VHFB)* 27(NC)*; U5 2(NC)* 3(NC)* 9(ASC_FB)* 12(NC)* 13(NC)* 16(VHFB)* 27(NC)*

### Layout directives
mark named LV_Nets: +5V, +12V, BOT-PWM, FLT_BOT, FLT_TOP, GND, RDY_BOT, RDY_TOP, TOP-PWM
mark named HV_Nets: BF_OFF_BOT, BF_OFF_TOP, BF_ON_BOT, BF_ON_TOP, BOT_Gate, BOT_OC, BOT_Source, BOT_VDD, BOT_VSS, MillerClamp_BOT, MillerClamp_TOP, OUTN_BOT, OUTN_TOP, OUTP_BOT, OUTP_TOP, TOP_Gate, TOP_OC, TOP_Source, TOP_VDD, TOP_VSS

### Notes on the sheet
- TOP SWITCH DRIVER
- BOTTOM SWITCH DRIVER

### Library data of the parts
C25 C26 C44 C45 = CMP-0007502-5: CAP, CERM, 2.2 uF, 50 V, +/- 10%, X5R, AEC-Q200 Grade 3, 0603; Manufacturer: MuRata; TaMin_C: -55°C; Polarized: N; SizeAreaWB_mm2: 4.68; Value1: Unknown; U/M: EA; Value: 2.2uF; TaMax_C: 85°C; SizeZ_mm: 1; SizeX_mm: 1.6; SizeY_mm: 0.8; SizeArea_mm2: 1.28; AEC Qualified: Y; Cap_F: 2.2µF; AEC Grade: 3; AEC Category: Q200
C27 C28 C46 C47 = CMP-0007194-4: CAP, CERM, 200 pF, 50 V, +/- 5%, C0G/NP0, 0603; Manufacturer: MuRata; TaMin_C: -55°C; Polarized: N; SizeAreaWB_mm2: 4.68; Value1: Unknown; U/M: EA; Value: 200pF; TaMax_C: 125°C; SizeZ_mm: 1; SizeX_mm: 1.6; SizeY_mm: 0.8; SizeArea_mm2: 1.28; AEC Category: Q200
C29 C42 = CMP-0091702-1: 4.7µF ±10% 25V Ceramic Capacitor X5R 0603 (1608 Metric); Manufacturer: Murata; AEC Qualified: No; SizeZ_mm: 1mm; TempCo: 15%
C30 C43 = CMP-0084679-1: as C1 on sheet TIDA-011011_DCDC_Supplies
C31-C34 = CMP-0006792-4: CAP, CERM, 56 pF, 50 V, +/- 1%, C0G/NP0, 0603; Manufacturer: AVX; TaMin_C: -55°C; Polarized: N; SizeAreaWB_mm2: 4.68; Value1: Unknown; U/M: EA; Value: 56pF; TaMax_C: 125°C; SizeZ_mm: 1; SizeX_mm: 1.6; SizeY_mm: 0.8; SizeArea_mm2: 1.28; AEC Category: Q200
C35 C48 = CMP-0093201-1: as C3 on sheet TIDA-011011_DCDC_Supplies
C36 C39 C49 C52 = CMP-0120154-1: 0.1 µF ±10% 50V Ceramic Capacitor X7R 0805 (2012 Metric); Manufacturer: KEMET; AEC Qualified: No; SizeZ_mm: 0.88mm; TempCo: 15%; ValueDisplayed: 0.1uF; Value: 100nF
C37 C50 = CMP-0122257-1: 1 µF ±10% 50V Ceramic Capacitor X7R 0603 (1608 Metric); Manufacturer: Samsung; AEC Grade: Grade 1; AEC Qualified: Yes; SizeZ_mm: 1mm; TempCo: 15%; ValueDisplayed: 1uF; Value: 1µF
C38 C51 = CMP-0094514-1: 10 µF ±5% 16V Ceramic Capacitor X7R 1206 (3216 Metric); Manufacturer: KEMET; SizeZ_mm: 1.8mm; TempCo: 15%; Cap_F: 10µF; Value: 10µF; AEC Qualified: Yes; AEC Grade: Grade 1
C40 C53 = CMP-0122429-1: 1 µF ±10% 16V Ceramic Capacitor X7S 0603 (1608 Metric); Manufacturer: Murata; AEC Qualified: No; Cap_F: 1µF; SizeZ_mm: 0.9mm; TempCo: 22%; Value: 1µF
C41 C54 = CMP-0006751-4: CAP, CERM, 100 pF, 25 V, +/- 10%, X7R, 0603; Manufacturer: AVX; TaMin_C: -55°C; Polarized: N; SizeAreaWB_mm2: 4.68; Value1: Unknown; U/M: EA; Value: 100pF; TaMax_C: 125°C; SizeZ_mm: 1; SizeX_mm: 1.6; SizeY_mm: 0.8; SizeArea_mm2: 1.28; AEC Category: Q200
C55-C58 = CMP-0093594-1: 0.1 µF ±10% 50V Ceramic Capacitor X7R 0603 (1608 Metric); Manufacturer: KEMET; AEC Grade: Grade 1; AEC Qualified: Yes; ValueDisplayed: 0.1uF; SizeZ_mm: 0.87mm; TempCo: 15%; Value: 100nF
D3-D5 = CMP-0002983-3: LED, Red, SMD; Manufacturer: OSRAM; Ir_A: 100µA; Tjmax_C: 95°C; Vf_V: 1.8V; Value1: W; Vr_V: 5V; Io_A: 20mA; Angle: 160
D6 D7 = CMP-0093310-1: Standard LEDs - SMD Green TOPLED E 1608; Manufacturer: Osram Opto; AEC Grade: Grade 2; LambdaP: 572nm; SizeZ_mm: 0.7mm; LuminousFlux_PhiV: 0.016-0.0295lm; Luminous Intensity: 4.5-9.7mcd; LambdaD: 570nm; Tjmax_C: 125°C; Angle: 120°; Led Orientation: Top View; Forward Current: 2mA; Vf_V: 1.8V; AEC Qualified: Yes; Vr_V: 12V
D8 D9 D13 D14 D18 D19 = CMP-0077081-2: Diode, Ultrafast, 1200 V, 1 A, SMA; Manufacturer: STMicroelectronics; AEC Qualified: N; TJmax_C: 175°C; SizeX_mm: 5.59; Green_Lifecycle: Not Set; Io_A: 1A; Value2: 1.9V; SizeY_mm: 2.92; SizeZ_mm: 2.87; AEC Category: Q101; Value: 1200V; SizeAreaWB_mm2: 37.3428; Vr_V: 1.2kV; Green_REACh: Incomplete; SizeArea_mm2: 16.3228
D10 D15 = CMP-0005892-4: Diode, Zener, 2.7 V, 300 mW, SOD-523; Manufacturer: Diodes Inc.; SizeY_mm: 0.9; AEC Category: Q101; SizeX_mm: 1.7; Power_W: 300mW; Value1: 0.3W; SizeZ_mm: 0.65; SizeAreaWB_mm2: 5.13; RJA_CperW: 417; SizeArea_mm2: 1.53
D11 D16 = CMP-0077574-3: Diode, Zener, 14 V, 500 mW, AEC-Q101, SOD-123; Manufacturer: Vishay-Semiconductor; Power_W: 500mW; Value1: 0.5W; AEC Qualified: Y; SizeZ_mm: 1.35; SizeAreaWB_mm2: 13.095; SizeX_mm: 3.85; AEC Category: Q101; RJA_CperW: 340; SizeY_mm: 1.7; SizeArea_mm2: 6.545
D12 D17 = CMP-0005417-4: Diode, Zener, 30 V, 1 W, PowerDI123; Manufacturer: Diodes Inc.; SizeX_mm: 3.7; Power_W: 1W; SizeY_mm: 1.78; AEC Category: Q101; RJA_CperW: 110; SizeArea_mm2: 6.586; SizeZ_mm: 0.98; SizeAreaWB_mm2: 13.066
J2 J6 = CMP-0075554-1: Connector, MMCX 50 ohm, TH; Manufacturer: Samtec; CT: False; Gender: Female
J3 J7 = CMP-0055713-1: Receptacle, 2.54mm, 2x2, Gold, TH; Manufacturer: Samtec; CNHeader: FALSE; Current_A: 4.7A; Gender: Female; Cert_CSA: Y; Voltage_V: 465V; CompType: Socket Strip; Row_Count: 2; RowSpacing_mm: 2.54; CT: TRUE
J4 J8 = CMP-0092582-1: as J1 on sheet TIDA-011011_DCDC_Supplies
J5 J9 = CMP-0078588-1: BNC JACK, 75 Ohm, Gold, R/A, TH; Manufacturer: Amphenol RF; Gender: Female
Q1 Q3 Q4 Q6 = CMP-0120256-1: N-Channel 40 V 8A (Ta), 19A (Tc) 2.3W (Ta), 15W (Tc) Surface Mount DFN2020MD-6; Manufacturer: Nexperia; AEC Qualified: Yes; QgTyp_nC: 11nC @ 10V; Rdson45_ohm: 17m; SizeZ_mm: 0.65mm; VdsMax_V: 1.2V; Vgs_V: 20V; ChMode: False; AEC Grade: Grade 0; Drain To Source Breakdown Voltage: 40V; Input Capacitace At Vds: 582pF @ 20V; Number Of Channels: 1; Pulse Drain Current: 76A; Reverse Recovery Charge: 5.4nC; Reverse Recovery Time: 12.8ns; Rthja Max: 57K/W; TaMax_C: +175°C; TaMin_C: -55°C; Threshold Vgs Max: 2.7V; Threshold Vgs Min: 1.3V; Transconductance: 33S; Turn Off Delay Time: 12ns; Turn On Delay Time: 2ns; Typ Forward Diode Voltage: 0.8V
Q2 Q5 = CMP-0120257-1: P-Channel 40 V 6A (Ta) 15W (Tc) Surface Mount DFN2020MD-6; Manufacturer: Nexperia; AEC Qualified: Yes; IdsMax_A: -6A; QgTyp_nC: 24nC @ -10V; Rdson45_ohm: 30m; SizeZ_mm: 0.65mm; VdsMax_V: -1.2V; Vgs_V: 20V; ChMode: False; AEC Grade: Grade 0; Drain To Source Breakdown Voltage: -40V; Input Capacitace At Vds: 1260pF @ -20V; Number Of Channels: 1; Power_W: 2.3W; Pulse Drain Current: -56A; Reverse Recovery Charge: 8nC; Reverse Recovery Time: 15.6ns; Rthja Max: 57K/W; TaMax_C: +175°C; TaMin_C: -55°C; Threshold Vgs Max: -2.7V; Threshold Vgs Min: -1.4V; Transconductance: 33S; Turn Off Delay Time: 35ns; Turn On Delay Time: 9ns; Typ Forward Diode Voltage: -0.8V
R2 R26 R33 R45 = CMP-0127666-1: 1 Ohms ±0.5% 0.52W Chip Resistor 1206 (3216 Metric) Anti-Sulfur, Automotive AEC-Q200, Moisture Resistant Thin Film; Manufacturer: Vishay; AEC Grade: Grade 0; AEC Qualified: Yes; Power_W: 520mW; SizeZ_mm: 0.65mm; TempCo: 25ppm/°C; VDC_V: 200V
R15 R16 R25 R31 R37-R39 R44 R50 R54-R56 = CMP-0125815-1: 10 kOhms ±1% 0.1W, 1/10W Chip Resistor 0603 (1608 Metric) Anti-Sulfur Thick Film; Manufacturer: Wurth Electronics; AEC Qualified: No; Power_W: 100mW; SizeZ_mm: 0.6mm; TempCo: 100ppm/°C; VDC_V: 75V
R17 = CMP-0022685-3: RES, 12.0 k, 1%, 0.1 W, 0603; Manufacturer: Panasonic; Power_W: 100mW; TempCo: 100 ppm/C; Value_Code: 12k0; U/M: EA; Value: 12.0k; Res_ohm: 12k; SizeX_mm: 1.6; SizeY_mm: 0.8; SizeZ_mm: 1; Value2: 0.1W; SizeArea_mm2: 1.28; VDC_V: 75V; AEC Category: Q200
R18 R19 = CMP-0122747-1: 8 kOhms ±0.1% 0.1W, 1/10W Chip Resistor 0603 (1608 Metric) Thin Film; Manufacturer: Yageo; AEC Qualified: No; Power_W: 100mW; SizeZ_mm: 0.55mm; TempCo: 50ppm/°C; VDC_V: 75V
R20 R21 = CMP-0125827-1: 24.9 kOhms ±1% 0.1W, 1/10W Chip Resistor 0603 (1608 Metric) Anti-Sulfur Thick Film; Manufacturer: Wurth Electronics; AEC Qualified: No; Power_W: 100mW; SizeZ_mm: 0.6mm; TempCo: 100ppm/°C; VDC_V: 75V
R22 R23 R29 R32 R41 R42 R48 R51 = CMP-0023691-3: RES, 120, 0.1%, 0.1 W, 0603; Manufacturer: Yageo America; Power_W: 100mW; TempCo: 25 ppm/C; Value_Code: 120R; U/M: EA; Value: 120; EIA_Code: E192; SizeX_mm: 1.6; SizeY_mm: 0.8; SizeZ_mm: 1; Value2: 0.1W; SizeArea_mm2: 1.28; VDC_V: 75V; AEC Category: Q200
R24 R43 = CMP-0016910-3: RES, 32.4, 1%, 0.25 W, AEC-Q200 Grade 0, 1206; Manufacturer: Vishay-Dale; Power_W: 250mW; TempCo: 100 ppm/C; Value_Code: 32R4; Value: 32.4; EIA_Code: E96; SizeX_mm: 3.2; SizeY_mm: 1.6; SizeZ_mm: 1.35; Value2: 0.25W; SizeArea_mm2: 5.12; AEC Qualified: Y; VDC_V: 200V; AEC Category: Q200; AEC Grade: 0
R27 R30 R46 R49 = CMP-0018677-3: RES, 3.3, 5%, 0.25 W, AEC-Q200 Grade 0, 1206; Manufacturer: Vishay-Dale; Power_W: 250mW; TempCo: 200 ppm/C; Value_Code: 3R30; Value: 3.3; EIA_Code: E24; SizeX_mm: 3.2; SizeY_mm: 1.6; SizeZ_mm: 1.35; Value2: 0.25W; SizeArea_mm2: 5.12; AEC Qualified: Y; VDC_V: 200V; AEC Category: Q200; AEC Grade: 0
R28 R47 = CMP-0024852-2: RES, 1.00 k, 0.5%, 0.1 W, 0603; Manufacturer: Yageo America; Power_W: 100mW; TempCo: 50 ppm/C; Value_Code: 1k00; U/M: EA; Value: 1.00k; EIA_Code: E192; Res_ohm: 1k; SizeX_mm: 1.6; SizeY_mm: 0.8; SizeZ_mm: 1; Value2: 0.1W; SizeArea_mm2: 1.28; VDC_V: 75V; AEC Category: Q200
R34 R53 = CMP-0094841-1: 10 Ohms ±1% 0.25W, 1/4W Chip Resistor 0603 (1608 Metric) Automotive AEC-Q200, Pulse Withstanding Thick Film; Manufacturer: ROHM; AEC Qualified: Yes; SizeZ_mm: 0.55mm; TempCo: 100ppm/°C; AEC Grade: Grade 0; Power_W: 250mW; VDC_V: 150V
R35 R36 = CMP-0025433-3: RES, 5.05 k, 0.5%, 0.1 W, 0603; Manufacturer: Yageo America; Power_W: 100mW; TempCo: 50 ppm/C; Value_Code: 5k05; U/M: EA; Value: 5.05k; EIA_Code: E192; SizeX_mm: 1.6; SizeY_mm: 0.8; SizeZ_mm: 1; Value2: 0.1W; SizeArea_mm2: 1.28; VDC_V: 75V; AEC Category: Q200
R40 R57 = CMP-0096427-1: 1 kOhms ±0.01% 0.125W, 1/8W Chip Resistor 0603 (1608 Metric) Anti-Sulfur, Moisture Resistant Thin Film; Manufacturer: Vishay; SizeZ_mm: 0.627mm; AEC Qualified: No; Power_W: 125mW; TempCo: 2ppm/°C; VDC_V: 75V
U4 U5 = CMP-0128293-1: Single Channel Isolated Pre-Driver for SiC/IGBT with Active Protection; Manufacturer: Texas Instruments; SizeZ_mm: 2.6mm; AEC Qualified: Yes; AEC Grade: Grade 1; Max Supply Voltage: 28V; Min Supply Voltage: 3V; Number Of Drivers: 1; Standoff Height: 0.05mm; TaMax_C: +125°C; TaMin_C: -40°C; TJmax_C: +150°C; Turn Off Delay Time: 65ns

## Sheet TIDA-011011_BlankSheet.SchDoc
size 431 x 279 mm; Date: Not shown in title block; ApprovedBy: Not shown in title block; CheckedBy: Not shown in title block; Author: Not shown in title block; CompanyName: Not shown in title block; Engineer: Not shown in title block; Organization: Not shown in title block; Address1: Not shown in title block; Address2: Not shown in title block; Address3: Not shown in title block; Address4: Not shown in title block; DocumentNumber: 2; Revision: Use project parameter SCH_Rev; SheetNumber: 3; SheetTotal: 4; PageSetup: Record=PageOptions¦CenterHorizontal=True¦CenterVertical=True¦PrintScale=1.00¦XCorrection=1.00¦YCorrection=1.00¦PrintKind=0¦BorderSize=5000000¦LeftOffset=0¦BottomOffset=0¦Orientation=2¦PaperLength=1000¦PaperWidth=1000¦Scale=100¦PaperSource=15¦PrintQuality=600¦MediaType=1¦DitherType=10¦PaperKind=Letter¦PrintScaleMode=1
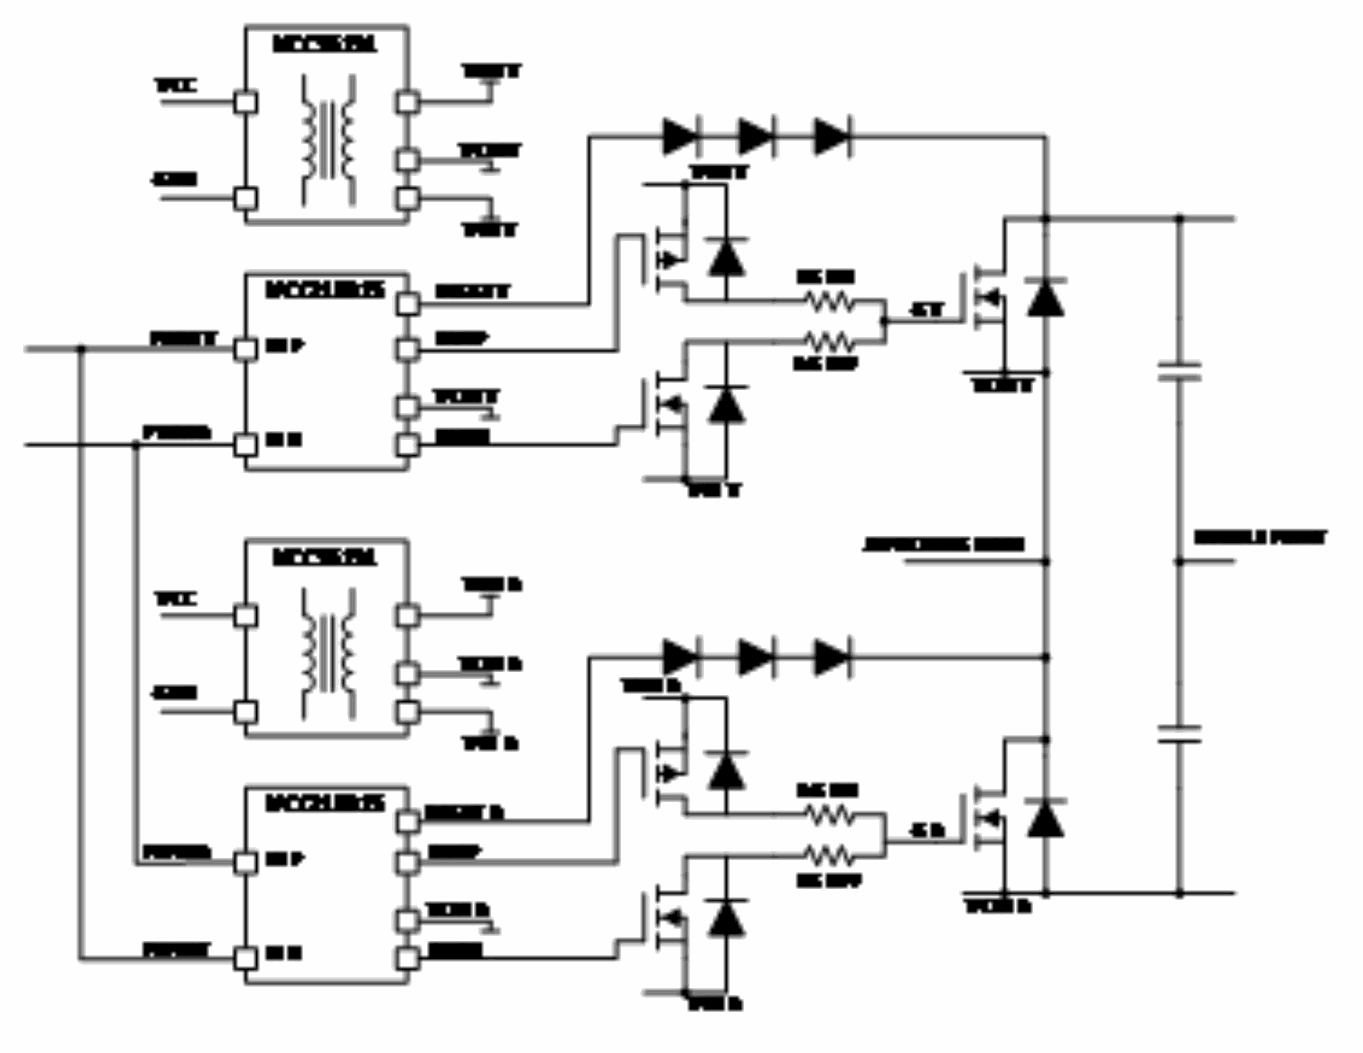
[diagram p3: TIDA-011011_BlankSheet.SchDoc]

## Sheet TIDA-011011_Hardware.SchDoc
size 431 x 279 mm; Date: Not shown in title block; ApprovedBy: Not shown in title block; CheckedBy: Not shown in title block; Author: Not shown in title block; CompanyName: Not shown in title block; Engineer: Not shown in title block; Organization: Not shown in title block; Address1: Not shown in title block; Address2: Not shown in title block; Address3: Not shown in title block; Address4: Not shown in title block; DocumentNumber: 3; Revision: Use project parameter SCH_Rev; SheetNumber: 4; SheetTotal: 4; PageSetup: Record=PageOptions¦CenterHorizontal=True¦CenterVertical=True¦PrintScale=1.00¦XCorrection=1.00¦YCorrection=1.00¦PrintKind=0¦BorderSize=5000000¦LeftOffset=0¦BottomOffset=0¦Orientation=2¦PaperLength=1000¦PaperWidth=1000¦Scale=100¦PaperSource=15¦PrintQuality=600¦MediaType=1¦DitherType=10¦PaperKind=Letter¦PrintScaleMode=1
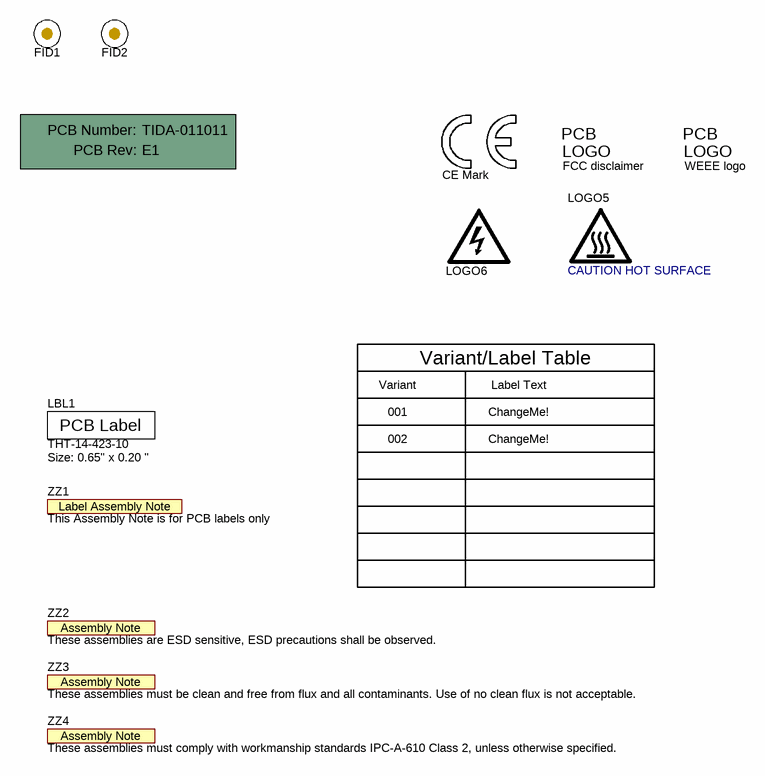
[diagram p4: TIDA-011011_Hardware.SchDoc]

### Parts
!PCB  Printed Circuit Board  (value not drawn)  (mechanical)
FID1  Fiducial  [Fiducial10-20]  (value not drawn)
FID2  Fiducial  [Fiducial10-20]  (value not drawn)
LBL1  THT-14-423-10  Note: Size: 0.65" x 0.20 "  [Label_650x200]
Logo2  CE Mark  [CE_Mark_5mm]  (no BOM)
Logo3  FCC disclaimer  [FCC_disclaimer]  (no BOM)
Logo4  WEEE logo  [WEEE_Minimum]  (no BOM)
LOGO5  CAUTION HOT SURFACE  [IEC_HotSurface_Medium]  (no BOM)
LOGO6  DANGER HIGH VOLTAGE  [IEC_HighVoltage_Medium]  (value not drawn)  (no BOM)
ZZ1  This Assembly Note is for PCB labels only  [AssemblyNoteLabel]  (no BOM)
ZZ2  These assemblies are ESD sensitive, ESD precautions shall be observed.  [AssemblyNote]  (no BOM)
ZZ3  These assemblies must be clean and free from flux and all contaminants. Use of no clean flux is not acceptable.  [AssemblyNote]  (no BOM)
ZZ4  These assemblies must comply with workmanship standards IPC-A-610 Class 2, unless otherwise specified.  [AssemblyNote]  (no BOM)

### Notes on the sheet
- Variant
- Variant/Label Table
- Label Text
- 001
- 002
- ChangeMe!

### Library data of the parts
!PCB = CMP-0003618-2: Manufacturer: Any; PartNumber: TIDA-011011
FID1 FID2 = CMP-0077181-1: Fiducial mark.  There is nothing to buy or mount.
LBL1 = CMP-0003625-1: Thermal Transfer Printable Labels, 0.650" W x 0.200" H - 10,000 per roll; Manufacturer: Brady; CompType: Label
Logo2 = CMP-0074844-1: SymbolCreator: a0412235
Logo3 = CMP-0074847-1: FCC_disclaimer; Library Reference: Logo
Logo4 = CMP-0074769-1
LOGO5 = CMP-0074837-2: IEC 61010-1 Hot Surface Warning; Manufacturer: Texas Instruments; SymbolCreator: a0412235; AEC Category: Q200; CompType: IC
LOGO6 = CMP-0074835-1: IEC 61010-1 High Voltage Warning; SymbolCreator: a0412235; Lib Reference: IEC_HighVoltage
ZZ1 = CMP-0003616-3
ZZ2 = CMP-0077236-1
ZZ3 = CMP-0077237-1
ZZ4 = CMP-0077238-1

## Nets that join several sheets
+5V: TIDA-011011_DCDC_Supplies (5 pins), TIDA-011011_Gate_Drivers (14 pins)
+12V: TIDA-011011_DCDC_Supplies (16 pins), TIDA-011011_Gate_Drivers (R17.2)
+18V_BOT: TIDA-011011_DCDC_Supplies (C14.1 C15.2 R10.2 U3.12), TIDA-011011_Gate_Drivers (10 pins)
+18V_TOP: TIDA-011011_DCDC_Supplies (C1.1 C2.2 R58.2 U1.12), TIDA-011011_Gate_Drivers (10 pins)
-5V_BOT: TIDA-011011_DCDC_Supplies (5 pins), TIDA-011011_Gate_Drivers (13 pins)
-5V_TOP: TIDA-011011_DCDC_Supplies (5 pins), TIDA-011011_Gate_Drivers (13 pins)
BOT_Source: TIDA-011011_DCDC_Supplies (8 pins), TIDA-011011_Gate_Drivers (20 pins)
GND: TIDA-011011_DCDC_Supplies (26 pins), TIDA-011011_Gate_Drivers (31 pins)
TOP_Source: TIDA-011011_DCDC_Supplies (8 pins), TIDA-011011_Gate_Drivers (20 pins)

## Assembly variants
001: not fitted FID1 FID2 FID3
